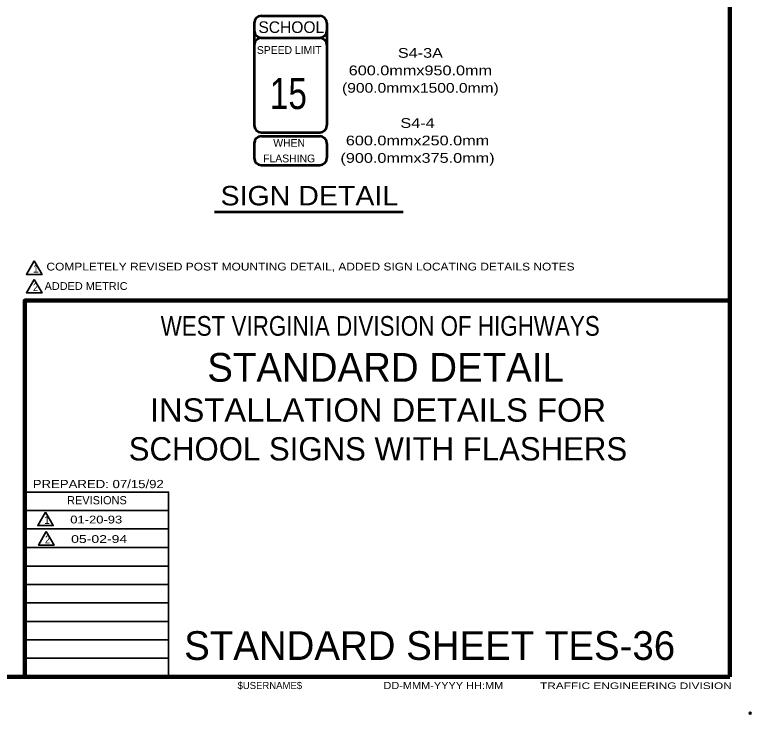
# Model space of a CAD drawing. Extents: x -35 to 821, y -10 to 534.
# Drawn here: x 593.3 to 821, y -10.4 to 205.9 of the extents above; entities that cross this region are included whole.
import ezdxf
from ezdxf.enums import TextEntityAlignment as Align

# ---------------------------------------------------------------- set-up
doc = ezdxf.new("R2010")
doc.units = 0
doc.header["$LTSCALE"] = 1.2
doc.header["$PDMODE"] = 32
doc.header["$PDSIZE"] = 0.6
doc.layers.add('1', color=7, linetype='Continuous', lineweight=35)
doc.layers.add('61', color=7, linetype='Continuous', lineweight=35)

msp = doc.modelspace()

# ---------------------------------------------------------------- linework, layer by layer
at = {"layer": '1', "lineweight": 158}
for q in [(814.384, 527.35), (814.384, 117.55), (22.784, 1.25)]:
    msp.add_line((814.384, 1.25), q, dxfattribs=at)
at = {"layer": '1', "lineweight": 13}
msp.add_line((814.384, 1.25), (814.384, 527.35), dxfattribs=at)
at = {"layer": '1', "lineweight": 53}
for p, q in [((669.574, 205.495), (687.574, 205.495)), ((667.324, 203.245), (667.324, 171.745)), ((689.824, 203.245), (689.824, 171.745)), ((669.574, 198.745), (687.574, 198.745)), ((669.574, 169.495), (687.574, 169.495)), ((669.574, 168.37), (687.574, 168.37)), ((667.324, 166.12), (667.324, 161.62)), ((689.824, 166.12), (689.824, 161.62)), ((669.574, 159.37), (687.574, 159.37)), ((655.025, 144.959), (713.428, 144.959))]:
    msp.add_line(p, q, dxfattribs=at)
at = {"layer": '1'}
for p, q in [((640.884, 52.65), (596.384, 52.65)), ((640.884, 46.95), (596.384, 46.95)), ((640.884, 41.15), (596.384, 41.15)), ((640.884, 35.45), (596.384, 35.45)), ((640.884, 29.75), (596.384, 29.75)), ((640.884, 24.05), (596.384, 24.05)), ((640.884, 18.35), (596.384, 18.35)), ((640.884, 12.65), (596.384, 12.65)), ((640.884, 6.95), (596.384, 6.95))]:
    msp.add_line(p, q, dxfattribs=at)
for points in [[(599.346, 129.785), (596.946, 125.628), (601.746, 125.628)], [(599.346, 124.079), (596.946, 119.922), (601.746, 119.922)], [(602.813, 52.13), (600.413, 47.973), (605.213, 47.973)], [(603.075, 46.113), (600.675, 41.956), (605.475, 41.956)]]:
    msp.add_lwpolyline(points, close=True, dxfattribs=at)
at = {"layer": '1', "lineweight": 158}
msp.add_lwpolyline([(596.384, 1.25), (596.384, 117.55), (814.384, 117.55)], dxfattribs=at)
at = {"layer": '1'}
msp.add_lwpolyline([(640.884, 1.25), (640.884, 58.35), (596.384, 58.35)], dxfattribs=at)
at = {"layer": '1', "lineweight": 53}
for centre, start, end in [((669.574, 203.245), 90, 180), ((687.574, 203.245), 0, 90), ((669.574, 200.995), 180, 270), ((687.574, 200.995), 270, 0), ((669.574, 196.495), 90, 180), ((687.574, 196.495), 0, 90), ((669.574, 171.745), 180, 270), ((687.574, 171.745), 270, 0), ((669.574, 166.12), 90, 180), ((687.574, 166.12), 0, 90), ((669.574, 161.62), 180, 270), ((687.574, 161.62), 270, 0)]:
    msp.add_arc(centre, 2.25, start, end, dxfattribs=at)
at = {"layer": '1'}
msp.add_point((820.684, -10.05), dxfattribs=at)
at = {"layer": '61', "lineweight": 53}
for q in [(661.684, 1.25), (661.684, 1.25), (661.684, 1.25), (661.984, 1.25), (661.984, 1.25)]:
    msp.add_line((814.384, 1.25), q, dxfattribs=at)

# ---------------------------------------------------------------- texts
at = {"layer": '1'}
for s, height, p in [('SCHOOL', 3.6, (668.633, 200.239)), ('SPEED LIMIT', 2.4, (668.162, 193.771)), ('1', 2.4, (598.942, 126.152)), ('REVISIONS', 2.537, (609.484, 54.55)), ('1', 2.4, (602.409, 48.497)), ('STANDARD SHEET TES-36', 8.881, (645.684, 6.45)), ('$USERNAME$', 2.2, (662.184, -2.55))]:
    msp.add_text(s, height=height, dxfattribs=at).set_placement(p)
for s, height, width, p in [('S4-3A', 3, 1.25, (718.705, 192.578)), ('600.0mmx950.0mm', 3, 1.25, (718.705, 187.178)), ('(900.0mmx1500.0mm)', 3, 1.2, (718.705, 181.778)), ('S4-4', 3, 1.25, (717.817, 170.911)), ('600.0mmx250.0mm', 3, 1.25, (717.817, 165.511)), ('(900.0mmx375.0mm)', 3, 1.25, (717.817, 160.111)), ('WEST VIRGINIA DIVISION OF HIGHWAYS', 6.089, 0.85, (706.284, 106.65)), ('INSTALLATION DETAILS FOR', 7.2, 1.05, (705.582, 80.104))]:
    msp.add_text(s, height=height, dxfattribs=dict(at, width=width)).set_placement(p, align=Align.CENTER)
for s, height, width, p in [('15', 9.6, 0.8, (672.203, 176.724)), ('SIGN DETAIL', 6, 1.1, (656.927, 146.956)), ('COMPLETELY REVISED POST MOUNTING DETAIL, ADDED SIGN LOCATING DETAILS NOTES', 2.4, 1.15, (603.112, 126.825)), ('ADDED METRIC', 2.4, 1.05, (602.534, 120.82)), ('2', 2.4, 0.9, (598.942, 120.446)), ('PREPARED: 07/15/92', 2.537, 1.2, (598.884, 59.55)), ('01-20-93', 2.4, 1.25, (610.479, 48.632)), ('2', 2.4, 0.9, (602.672, 42.481)), ('05-02-94', 2.4, 1.35, (610.742, 42.615)), ('DD-MMM-YYYY HH:MM', 2.2, 1.15, (707.284, -2.55)), ('TRAFFIC ENGINEERING DIVISION', 2.031, 1.35, (755.684, -2.55))]:
    msp.add_text(s, height=height, dxfattribs=dict(at, width=width)).set_placement(p)
for s, height, p in [('WHEN', 2.4, (678.13, 165.055)), ('FLASHING', 2.4, (678.13, 160.255)), ('STANDARD DETAIL', 8.881, (707.934, 92.45)), ('SCHOOL SIGNS WITH FLASHERS', 7.2, (705.582, 68.104))]:
    msp.add_text(s, height=height, dxfattribs=at).set_placement(p, align=Align.CENTER)

doc.saveas('drawing.dxf')
